Omron CX-Programmer project NuevoProyecto (CX-Programmer 9.50)

# PLC NewPLC1: CP1L-E EM

## Program P17_1 (cyclic task 0)
Local symbols
EV1 100.01 BOOL
EV2 100.02 BOOL
EV3 100.03 BOOL
Etapa_0 10.00 BOOL
Etapa_1 10.01 BOOL
Etapa_2 10.02 BOOL
Etapa_3 10.03 BOOL
Etapa_4 10.04 BOOL
Etapa_5 10.05 BOOL
Etapa_6 10.06 BOOL
Etapa_7 10.07 BOOL
F1 0.02 BOOL
FSF1 15.00 BOOL  ; Flanco Subida F1
MC 100.00 BOOL
S_1 0.01 BOOL
m 0.00 BOOL

### Section Sección1_Programa_principal
; Programa principal (Etapas 0 ... 23)

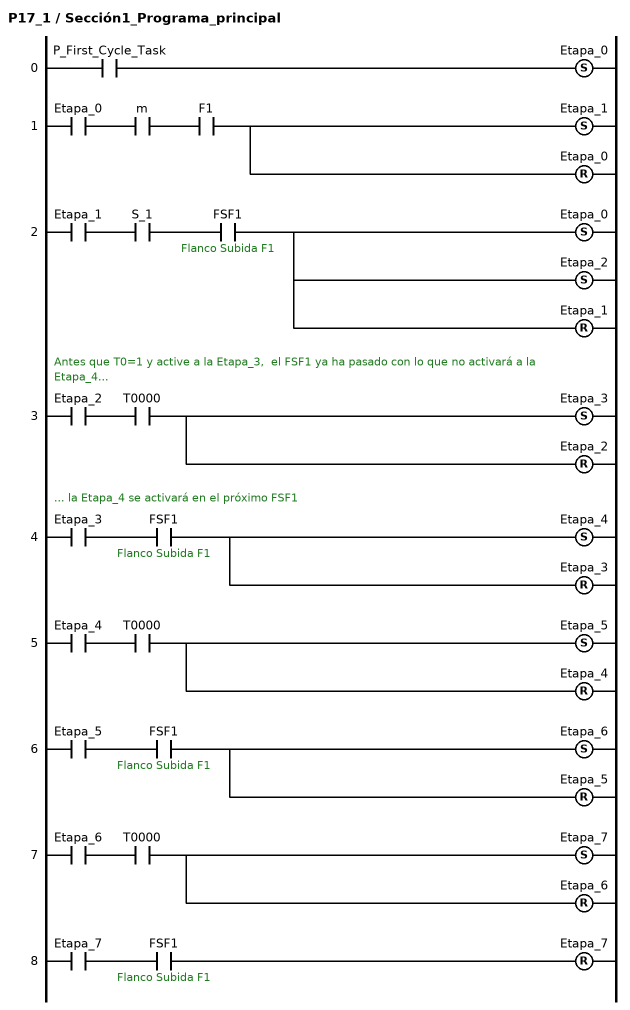
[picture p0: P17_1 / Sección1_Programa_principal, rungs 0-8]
; rung 0
LD P_First_Cycle_Task
SET Etapa_0
; rung 1
LD Etapa_0
AND m
AND F1
SET Etapa_1
RSET Etapa_0
; rung 2
LD Etapa_1
AND S_1
AND FSF1  ; Flanco Subida F1
SET Etapa_0
SET Etapa_2
RSET Etapa_1
; rung 3: Antes que T0=1 y active a la Etapa_3,  el FSF1 ya ha pasado con lo que no activará a la Etapa_4...
LD Etapa_2
AND T0000
SET Etapa_3
RSET Etapa_2
; rung 4: ... la Etapa_4 se activará en el próximo FSF1
LD Etapa_3
AND FSF1  ; Flanco Subida F1
SET Etapa_4
RSET Etapa_3
; rung 5
LD Etapa_4
AND T0000
SET Etapa_5
RSET Etapa_4
; rung 6
LD Etapa_5
AND FSF1  ; Flanco Subida F1
SET Etapa_6
RSET Etapa_5
; rung 7
LD Etapa_6
AND T0000
SET Etapa_7
RSET Etapa_6
; rung 8
LD Etapa_7
AND FSF1  ; Flanco Subida F1
RSET Etapa_7

### Section Sección2_Temporizador

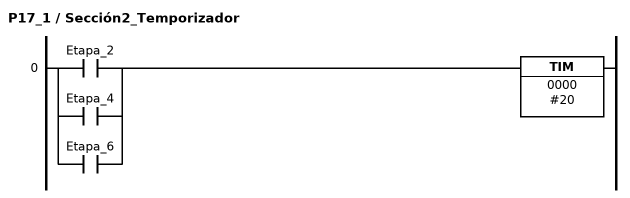
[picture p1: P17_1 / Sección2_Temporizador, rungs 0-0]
; rung 0
LD Etapa_2
OR Etapa_4
OR Etapa_6
TIM 0000 #20

### Section Sección3_FSF1

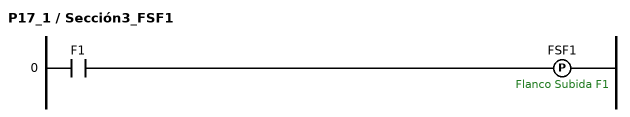
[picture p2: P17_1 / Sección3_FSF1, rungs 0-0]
; rung 0
LD F1
DIFU(013) FSF1  ; Flanco Subida F1

### Section Sección4_Salidas

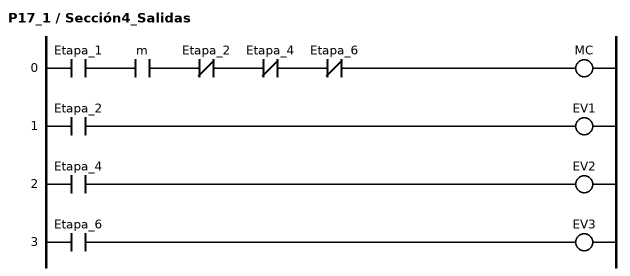
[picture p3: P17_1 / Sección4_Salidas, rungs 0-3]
; rung 0
LD Etapa_1
AND m
ANDNOT Etapa_2
ANDNOT Etapa_4
ANDNOT Etapa_6
OUT MC
; rung 1
LD Etapa_2
OUT EV1
; rung 2
LD Etapa_4
OUT EV2
; rung 3
LD Etapa_6
OUT EV3

### Section Sección5_END
; rung 0: Fin de programa
END(001)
